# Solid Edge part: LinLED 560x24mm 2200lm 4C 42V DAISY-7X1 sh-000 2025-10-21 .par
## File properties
Author: patryk.ciesielski
Template: iso metric part.par
Last saved by: patryk.ciesielski
Revision: 1
Application: Solid Edge
Gęstość: 0.000 kg/m^3
Dokładność: 0.990
Username: patryk.ciesielski
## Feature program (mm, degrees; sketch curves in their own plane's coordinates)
body "unnamed Body 1"
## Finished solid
Body 1: solid body, 2100 faces, 6100 edges, 4206 vertices.
  Faces by surface: plane 1634, cylinder 408, swept 28, sphere 18, cone 4, spline 4, torus 4
  Edges by curve: line 4936, circle 874, ellipse 154, curve on surface 136
Bounding box of the edges (mm; curved faces can reach further): 558.000 x 24.000 x 4.330, from (-279, -12, -1.6) to (279, 12, 2.73).
Cylindrical faces by radius (mm): R0.0495 x4, R0.0647 x8, R0.0649 x8, R0.1 x20, R0.1164 x4, R0.1314 x16, R0.1729 x4, R0.2 x224, R0.2289 x4, R0.47 x8, R0.5 x56, R0.6 x4, R0.625 x4, R0.75 x8, R1 x16, R1.0277 x4, R1.05 x4, R1.7 x12
Conical faces (half-angle, radius in mm at the cone's reference point): 36.872 deg R0.8536 x4
Toroidal faces (ring radius, tube radius in mm): R1.2 r0.1 x4
Spherical faces by radius (mm): R0.1 x10, R0.5 x8
Planar faces by outward normal: +x 141, +y 149, +z 309, -x 141, -y 149, -z 13, oblique 732
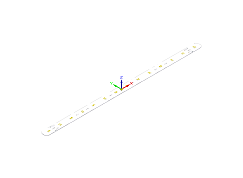
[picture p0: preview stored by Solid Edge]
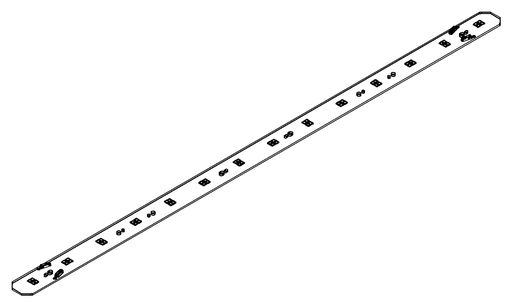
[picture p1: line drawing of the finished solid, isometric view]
